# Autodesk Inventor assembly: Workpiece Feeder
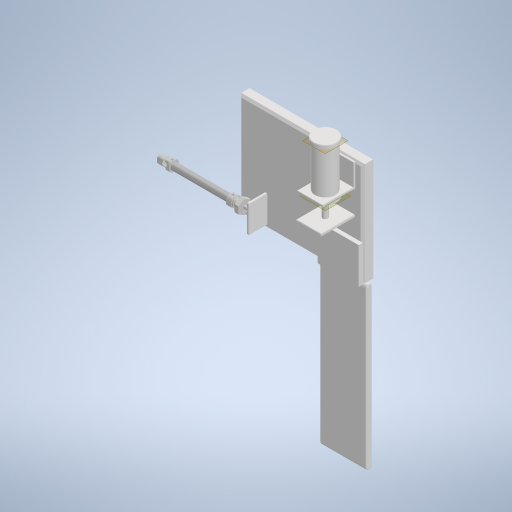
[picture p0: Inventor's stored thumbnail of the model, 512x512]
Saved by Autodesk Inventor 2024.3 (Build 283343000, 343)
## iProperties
Created: 2024-12
Part Number: Workpiece Feeder
Document SubType Name: Assembly
Designer: ruhr
Author: ruhr
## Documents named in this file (6)
- C:\Users\ruhr\OneDrive - Mercantec\Dokumenter\DigiTwinVideo\Workpiece Feeder.iam
- C:\Users\ruhr\OneDrive - Mercantec\Dokumenter\DigiTwinVideo\Machine base.ipt
- C:\Users\ruhr\OneDrive - Mercantec\Dokumenter\DigiTwinVideo\Workpiece.ipt
- C:\Users\ruhr\OneDrive - Mercantec\Dokumenter\DigiTwinVideo\Pusher 1.iam
- C:\Users\ruhr\OneDrive - Mercantec\Dokumenter\DigiTwinVideo\Conveyor.ipt
- C:\Users\ruhr\OneDrive - Mercantec\Dokumenter\DigiTwinVideo\PARTserver0202411291136211484952210e898ce\19193_DSNU-12-80-P-A\19193_DSNU-12-80-P-A\19193_DSNU-12-80-P-A.iam
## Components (5 placed, 5 different names)
1. Machine base:1 — Flush:1, Flush:2, Rigid:1, Rigid:2, Mate:1, Mate:2
2. Workpiece:1 — Flush:1, Flush:2, Rigid:1
3. Pusher 1:1 [sub-assembly] — Rigid:2
4. Conveyor:1 — Mate:1
5. 19193_DSNU-12-80-P-A:1 [sub-assembly] — Mate:2
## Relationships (6: Flush 2, WeldJoint 2, Mate 2)
- Flush:1: Machine base:1 ↔ Workpiece:1
- Flush:2: Machine base:1 ↔ Workpiece:1
- Rigid:1 [WeldJoint]: Machine base:1 ↔ Workpiece:1
- Rigid:2 [WeldJoint]: Machine base:1 ↔ Pusher 1:1
- Mate:1: Machine base:1 ↔ Conveyor:1
- Mate:2: Machine base:1 ↔ 19193_DSNU-12-80-P-A:1
